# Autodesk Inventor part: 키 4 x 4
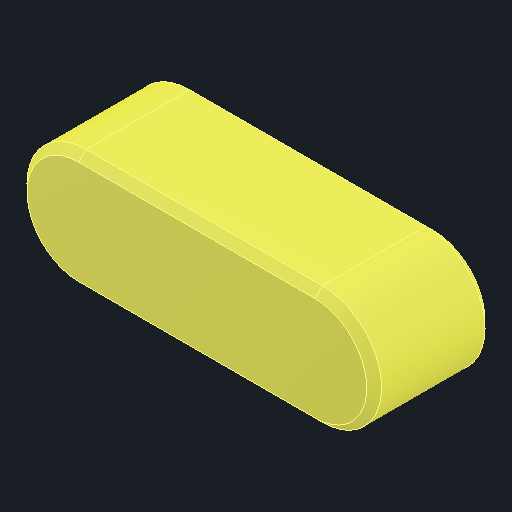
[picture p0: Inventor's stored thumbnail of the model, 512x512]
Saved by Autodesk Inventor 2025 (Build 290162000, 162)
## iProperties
Created: 2025-08
Part Number: 키 4 x 4
Material: 강철, 연강
Description: 키 및 해당 키홈
Document SubType Name: Modeling
Designer: infra005
Density: 7.86 g/cm^3
Appearance: 기본값
Author: jhkim
Sending System: Autodesk Inventor 2026
Preprocessor: ST-DEVELOPER v20.1
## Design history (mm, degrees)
feature "Solid1"
node "솔리드1"
